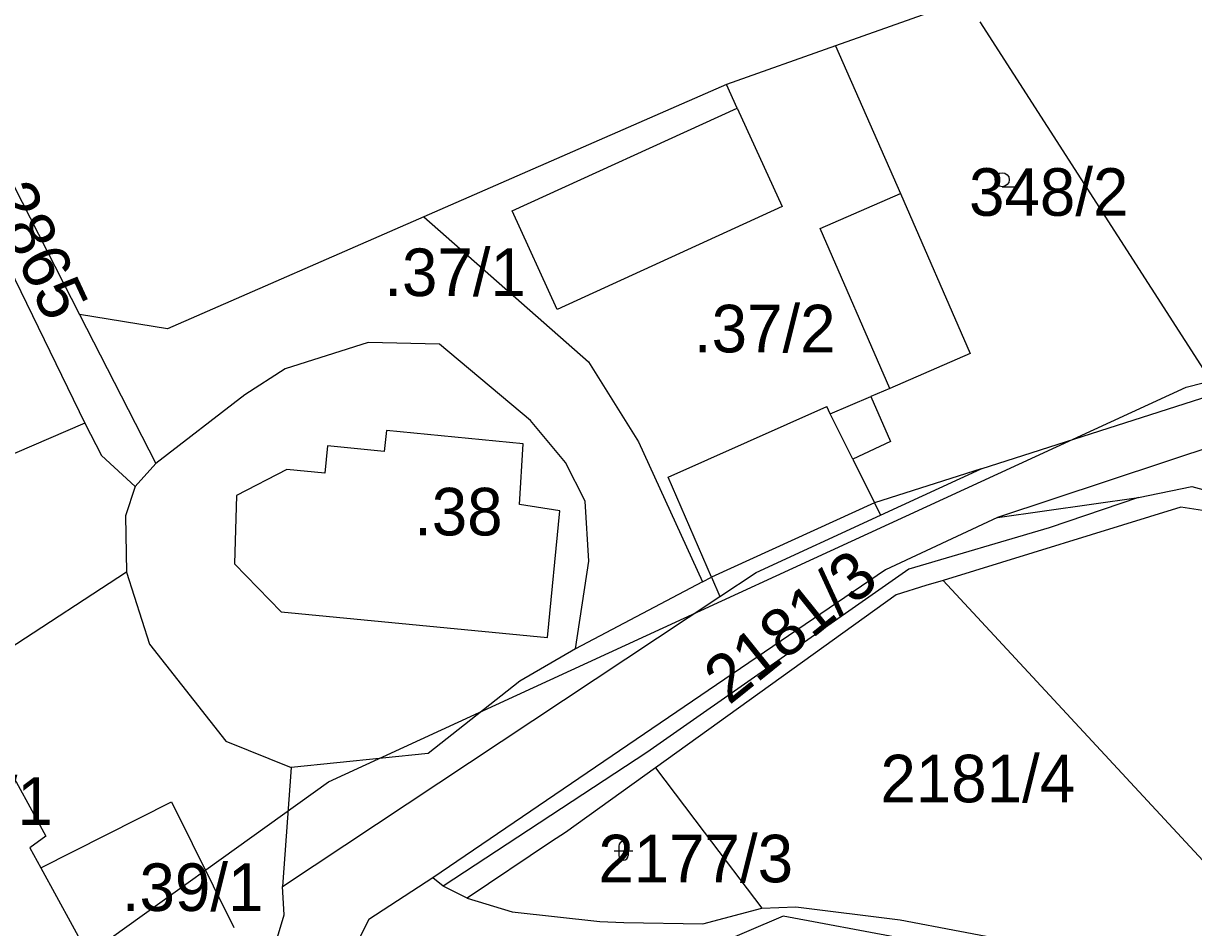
# Model space of a CAD drawing. Extents: x -564810 to -550519, y -1045831 to -1034011.
# Drawn here: x -553266.8 to -553141.5, y -1036707.9 to -1036611.1 of the extents above; entities that cross this region are included whole.
import ezdxf

# ---------------------------------------------------------------- set-up
doc = ezdxf.new("R2010")
doc.units = 0
for name, color, linetype in [('KN stav', 7, 'Continuous'), ('Parcelní čísla', 7, 'Continuous'), ('STG', 7, 'Continuous'), ('vodní toky', 7, 'Continuous'), ('Vrstva 22', 7, 'Continuous'), ('Vrstva 4', 7, 'Continuous'), ('zamokř ploch', 7, 'Continuous')]:
    doc.layers.add(name, color=color, linetype=linetype)

msp = doc.modelspace()

# ---------------------------------------------------------------- linework, layer by layer
at = {"layer": 'KN stav'}
for p, q in [((-553278.1, -1036608.45), (-553260.82, -1036642.24)), ((-553165.82, -1036608.46), (-553179.86, -1036613.46)), ((-553280.99, -1036611.25), (-553260.24, -1036653.89)), ((-553164.39, -1036610.89), (-553138.82, -1036650.66)), ((-553179.86, -1036613.46), (-553191.53, -1036617.62)), ((-553179.86, -1036613.46), (-553172.89, -1036629.3)), ((-553191.53, -1036617.62), (-553223.94, -1036631.79)), ((-553172.89, -1036629.3), (-553165.42, -1036646.44)), ((-553223.94, -1036631.79), (-553251.38, -1036643.79)), ((-553223.94, -1036631.79), (-553206.29, -1036647.32)), ((-553260.82, -1036642.24), (-553252.65, -1036658.2)), ((-553251.38, -1036643.79), (-553260.82, -1036642.24)), ((-553229.88, -1036645.25), (-553238.79, -1036648.09)), ((-553222.26, -1036645.43), (-553229.88, -1036645.25)), ((-553212.52, -1036653.61), (-553222.26, -1036645.43)), ((-553165.42, -1036646.44), (-553174.02, -1036650.19)), ((-553206.29, -1036647.32), (-553200.96, -1036655.91)), ((-553238.79, -1036648.09), (-553243.1, -1036650.85)), ((-553174.02, -1036650.19), (-553176.05, -1036651.05)), ((-553243.1, -1036650.85), (-553252.65, -1036658.2)), ((-553176.05, -1036651.05), (-553173.95, -1036655.86)), ((-553164.24, -1036658.78), (-553138.82, -1036650.66)), ((-553122.12, -1036650.58), (-553162.51, -1036664)), ((-553260.24, -1036653.89), (-553274.28, -1036659.95)), ((-553260.24, -1036653.89), (-553258.47, -1036657.37)), ((-553208.76, -1036658.11), (-553212.52, -1036653.61)), ((-553200.96, -1036655.91), (-553194.1, -1036670.9)), ((-553173.95, -1036655.86), (-553178, -1036657.74)), ((-553258.47, -1036657.37), (-553254.86, -1036660.68)), ((-553178, -1036657.74), (-553175.67, -1036662.43)), ((-553252.65, -1036658.2), (-553254.86, -1036660.68)), ((-553206.64, -1036662.25), (-553208.76, -1036658.11)), ((-553175.02, -1036663.74), (-553164.24, -1036658.78)), ((-553254.86, -1036660.68), (-553255.87, -1036663.81)), ((-553147.4, -1036661.87), (-553141.69, -1036660.67)), ((-553141.69, -1036660.67), (-553136.74, -1036662.04)), ((-553206.28, -1036668.68), (-553206.64, -1036662.25)), ((-553175.67, -1036662.43), (-553175.02, -1036663.74)), ((-553142.88, -1036662.89), (-553168.31, -1036670.73)), ((-553162.51, -1036664), (-553147.4, -1036661.87)), ((-553137.25, -1036663.75), (-553142.88, -1036662.89)), ((-553255.87, -1036663.81), (-553255.78, -1036669.84)), ((-553188.34, -1036669.89), (-553175.02, -1036663.74)), ((-553162.51, -1036664), (-553174.48, -1036669.61)), ((-553207.7, -1036678.06), (-553206.28, -1036668.68)), ((-553255.78, -1036669.84), (-553268.44, -1036678.15)), ((-553255.78, -1036669.84), (-553253.3, -1036677.55)), ((-553174.48, -1036669.61), (-553201.19, -1036687.78)), ((-553194.1, -1036670.9), (-553193.13, -1036670.39)), ((-553193.13, -1036670.39), (-553192.23, -1036672.47)), ((-553192.23, -1036672.47), (-553188.34, -1036669.89)), ((-553194.1, -1036670.9), (-553207.7, -1036678.06)), ((-553170.17, -1036671.3), (-553173.37, -1036672.29)), ((-553168.31, -1036670.73), (-553170.17, -1036671.3)), ((-553130.67, -1036711.39), (-553168.31, -1036670.73)), ((-553239.07, -1036703.51), (-553192.23, -1036672.47)), ((-553173.37, -1036672.29), (-553199.12, -1036690.8)), ((-553253.3, -1036677.55), (-553245.13, -1036687.94)), ((-553245.13, -1036687.94), (-553238.15, -1036690.79)), ((-553201.19, -1036687.78), (-553222.96, -1036702.59)), ((-553269.1, -1036689.57), (-553264.42, -1036698.14)), ((-553238.15, -1036690.79), (-553239.07, -1036703.51)), ((-553199.12, -1036690.8), (-553208.78, -1036697.74)), ((-553199.12, -1036690.8), (-553193.9, -1036697.7)), ((-553264.42, -1036698.14), (-553266.14, -1036699.37)), ((-553208.78, -1036697.74), (-553210.25, -1036698.72)), ((-553193.9, -1036697.7), (-553187.75, -1036705.86)), ((-553266.14, -1036699.37), (-553264.95, -1036701.53)), ((-553210.25, -1036698.72), (-553219.31, -1036704.78)), ((-553264.95, -1036701.53), (-553257.51, -1036715.1)), ((-553222.96, -1036702.59), (-553229.83, -1036707.06)), ((-553221.87, -1036703.5), (-553222.96, -1036702.59)), ((-553238.91, -1036706.57), (-553239.07, -1036703.51)), ((-553219.31, -1036704.78), (-553221.87, -1036703.5)), ((-553219.31, -1036704.78), (-553214.46, -1036706.24)), ((-553240.82, -1036713.06), (-553238.91, -1036706.57)), ((-553214.46, -1036706.24), (-553205.09, -1036707.28)), ((-553194.06, -1036707.52), (-553187.75, -1036705.86)), ((-553187.75, -1036705.86), (-553184.1, -1036705.71)), ((-553184.1, -1036705.71), (-553172.92, -1036707.08)), ((-553229.83, -1036707.06), (-553233.12, -1036713.57)), ((-553205.09, -1036707.28), (-553202.51, -1036707.38)), ((-553202.51, -1036707.38), (-553194.06, -1036707.52)), ((-553172.92, -1036707.08), (-553147.32, -1036711.94))]:
    msp.add_line(p, q, dxfattribs=at)
at = {"layer": 'STG'}
msp.add_lwpolyline([(-553913.89, -1037214.19), (-553796.31, -1037140.69), (-553706.3, -1037067.18), (-553629.14, -1036991.84), (-553566.68, -1036914.66), (-553476.66, -1036833.81), (-553318.67, -1036752.96), (-553234.16, -1036692.32), (-553142.31, -1036650.05), (-553048.61, -1036626.16), (-552953.09, -1036624.32), (-552903.48, -1036624.32), (-552861.23, -1036602.27), (-552798.77, -1036576.55), (-552738.15, -1036530.61), (-552646.29, -1036431.38), (-552581.99, -1036368.9), (-552545.25, -1036306.42), (-552506.67, -1036223.73), (-552482.79, -1036161.25), (-552440.54, -1036117.15)], dxfattribs=at)
at = {"layer": 'vodní toky'}
msp.add_lwpolyline([(-553172.85, -1036709.05), (-553185.46, -1036706.72), (-553193.07, -1036709.96)], dxfattribs=at)
at = {"layer": 'Vrstva 4'}
for p, q in [((-553190.38, -1036620.14), (-553191.53, -1036617.62)), ((-553214.49, -1036631.14), (-553190.38, -1036620.14)), ((-553190.38, -1036620.14), (-553185.56, -1036630.7)), ((-553181.49, -1036633.05), (-553172.89, -1036629.3)), ((-553209.67, -1036641.7), (-553214.49, -1036631.14)), ((-553185.56, -1036630.7), (-553209.67, -1036641.7)), ((-553174.02, -1036650.19), (-553181.49, -1036633.05)), ((-553180.41, -1036652.88), (-553176.06, -1036651.04)), ((-553197.78, -1036659.67), (-553180.79, -1036652.12)), ((-553180.41, -1036652.88), (-553180.79, -1036652.12)), ((-553178, -1036657.74), (-553180.41, -1036652.88)), ((-553227.95, -1036654.69), (-553228.17, -1036656.92)), ((-553213.31, -1036656.11), (-553227.95, -1036654.69)), ((-553234.25, -1036656.33), (-553234.53, -1036659.24)), ((-553228.17, -1036656.92), (-553234.25, -1036656.33)), ((-553213.68, -1036662.62), (-553213.31, -1036656.11)), ((-553238.6, -1036658.84), (-553243.98, -1036661.65)), ((-553234.53, -1036659.24), (-553238.6, -1036658.84)), ((-553164.24, -1036658.77), (-553175.67, -1036662.42)), ((-553193.13, -1036670.39), (-553197.78, -1036659.67)), ((-553243.98, -1036661.65), (-553244.21, -1036668.97)), ((-553209.38, -1036663.28), (-553213.68, -1036662.62)), ((-553175.67, -1036662.42), (-553193.13, -1036670.39)), ((-553147.4, -1036661.87), (-553156.96, -1036665.11)), ((-553210.69, -1036676.86), (-553209.38, -1036663.28)), ((-553156.96, -1036665.11), (-553171.98, -1036669.55)), ((-553244.21, -1036668.97), (-553239.22, -1036674.1)), ((-553171.98, -1036669.55), (-553200.05, -1036689.18)), ((-553239.22, -1036674.1), (-553210.69, -1036676.86)), ((-553207.7, -1036678.05), (-553213.66, -1036681.53)), ((-553213.66, -1036681.53), (-553223.48, -1036689.27)), ((-553223.48, -1036689.27), (-553238.15, -1036690.79)), ((-553200.05, -1036689.18), (-553221.87, -1036703.5)), ((-553264.95, -1036701.53), (-553250.95, -1036694.44)), ((-553250.95, -1036694.44), (-553244.29, -1036707.93))]:
    msp.add_line(p, q, dxfattribs=at)
at = {"layer": 'zamokř ploch'}
for p, q in [((-553161.99, -1036628.56), (-553160.39, -1036628.56)), ((-553203.06, -1036699.2), (-553203.06, -1036700.2)), ((-553202.06, -1036699.2), (-553202.06, -1036700.2)), ((-553203.56, -1036699.7), (-553201.56, -1036699.7))]:
    msp.add_line(p, q, dxfattribs=at)
msp.add_circle((-553161.99, -1036627.81), 0.75, dxfattribs=at)
for centre, start, end in [((-553202.56, -1036699.2), 0, 180), ((-553202.56, -1036700.2), 180, 0)]:
    msp.add_arc(centre, 0.5, start, end, dxfattribs=at)

# ---------------------------------------------------------------- texts
at = {"layer": 'Parcelní čísla'}
for s, p in [('348/2', (-553165.55, -1036631.68)), ('2181/4', (-553175.04, -1036694.51)), ('356/1', (-553280.74, -1036696.93)), ('2177/3', (-553205.25, -1036703.08))]:
    msp.add_text(s, height=5.1, dxfattribs=at).set_placement(p)
for s, rotation, p in [('2865', 294.9645, (-553270.71, -1036629.52)), ('2181/3', 38.7604, (-553191.25, -1036684.16)), ('2181/3', 38.7604, (-553191.25, -1036684.15))]:
    msp.add_text(s, height=5.1, rotation=rotation, dxfattribs=at).set_placement(p)
at = {"layer": 'Vrstva 22'}
for s, p in [('.37/1', (-553228.17, -1036640.28)), ('.37/2', (-553195.01, -1036646.31)), ('.38', (-553224.98, -1036665.92)), ('.39/1', (-553256.28, -1036706.15))]:
    msp.add_text(s, height=5.1, dxfattribs=at).set_placement(p)

doc.saveas('drawing.dxf')
